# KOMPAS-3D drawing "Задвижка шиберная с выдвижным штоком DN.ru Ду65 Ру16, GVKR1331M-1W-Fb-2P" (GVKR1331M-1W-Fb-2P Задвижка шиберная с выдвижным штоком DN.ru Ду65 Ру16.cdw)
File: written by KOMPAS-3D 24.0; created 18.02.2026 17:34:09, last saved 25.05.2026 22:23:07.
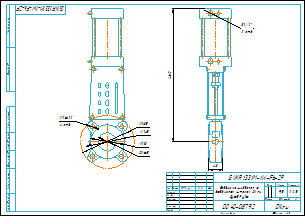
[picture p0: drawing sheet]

Document properties: Автор: R2D2; Форматы листов документа: A3; Полное имя файла: GVKR1331M-1W-Fb-2P Задвижка шиберная с выдвижным штоком DN.ru Ду65 Ру16.m3d; Масса: 9.5; Наименование: Задвижка шиберная с выдвижным штоком DN.ru Ду65 Ру16; Количество листов документа: 1; Примечание: D040-08792

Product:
- Part/product: Задвижка шиберная с выдвижным штоком DN.ru Ду65 Ру16  | designation GVKR1331M-1W-Fb-2P
    Масса: 9.5
    Раздел спецификации: Прочие изделия
    Примечание: D040-08792

Views: Вид 1, Сзади, Проекционный вид 2
Referenced files in E:\Работа\Зайцев\GVKR1331N-2W-Fb-S Задвижка шиберная с выдвижным штоком DN.ru Ду50-300 Ру10\DN50\: GVKR1331N-2W-Fb-S Задвижка шиберная DN.ru Ду50 Ру10.m3d
Referenced files in E:\Работа\Зайцев\GVKR1331M-1W-Fb-2P Задвижка шиберная с выдвижным штоком DN.ru Ду50-300 Ру16-10-6 с пневмоприводом\исходные материалы\DN65\DN65\: GVKR1331M-1W-Fb-2P Задвижка шиберная с выдвижным штоком DN.ru Ду65 Ру16.m3d
Referenced files in E:\Работа\Зайцев\Для компаса\: чертеж DN.ru А3.cdt
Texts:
  GVKR1331M-1W-Fb-2P
  чертеж DN.ru А3.cdt
  Задвижка шиберная с
  выдвижным штоком DN.ru
  Ду65 Ру16
  Задвижка шиберная с выдвижным штоком DN.ru Ду65 Ру16
  GVKR1331M-1W-Fb-2P Задвижка шиберная с выдвижным штоком DN.ru Ду65 Ру16
Dimensions and other numbers on the sheet: 0; 3; 2; 4; 185; 16; 4 отв.; 145; 65; 118; 7; 460; 48; 2 отв.; 1:2,5; 1; 9,5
